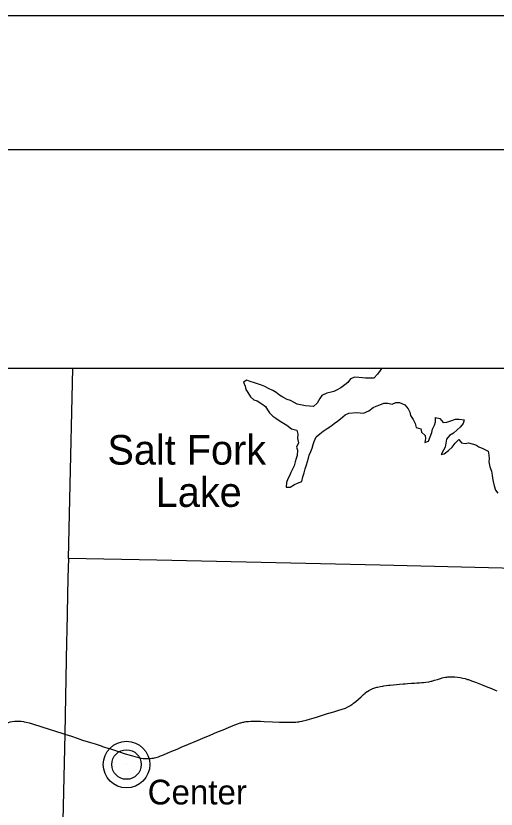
# Model space of a CAD drawing. Extents: x -29.6 to 34, y 0 to 22.
# Drawn here: x 7.023 to 8.82, y 19.03 to 22 of the extents above; entities that cross this region are included whole.
import ezdxf

# ---------------------------------------------------------------- set-up
doc = ezdxf.new("R2010")
doc.units = 0
for name, color, linetype in [('GM_X_Major_Lake', 7, 'Continuous'), ('GM_X_Major_Lake_Text', 7, 'Continuous'), ('GM_X_Township', 7, 'Continuous'), ('GM_X_Unincorporated', 7, 'Continuous'), ('GM_X_Unincorporated_Location', 7, 'Continuous'), ('GM_X_Unincorporated_Text', 7, 'Continuous'), ('GM_X_US_Route', 7, 'Continuous'), ('SH_Border', 7, 'Continuous'), ('SH_Cut_Line', 7, 'Continuous'), ('SH_Text', 7, 'Continuous')]:
    doc.layers.add(name, color=color, linetype=linetype)

msp = doc.modelspace()

# ---------------------------------------------------------------- linework, layer by layer
at = {"layer": 'GM_X_Major_Lake'}
for points in [[(8.3904, 20.6798), (8.3859, 20.672), (8.3754, 20.6581), (8.3617, 20.6442), (8.3493, 20.6437), (8.3312, 20.6436), (8.3196, 20.6448), (8.3064, 20.6461), (8.2917, 20.6477), (8.2749, 20.6414), (8.2653, 20.6271), (8.2534, 20.619), (8.2389, 20.6074), (8.2252, 20.5993), (8.2128, 20.5939), (8.1982, 20.5902), (8.1858, 20.587), (8.1682, 20.5789), (8.1603, 20.5669), (8.1507, 20.5499)], [(8.1507, 20.5499), (8.137, 20.5378), (8.1211, 20.5386), (8.106, 20.5394), (8.0758, 20.5467), (8.0647, 20.552), (8.0505, 20.5594), (8.0376, 20.5642), (8.0221, 20.5725), (8.0096, 20.5795), (7.9967, 20.5901), (7.9847, 20.5976), (7.9683, 20.6046), (7.954, 20.6129), (7.9421, 20.6177), (7.931, 20.6216), (7.9159, 20.626), (7.8994, 20.6316), (7.8875, 20.6355), (7.8742, 20.6283), (7.881, 20.6133), (7.8828, 20.6017), (7.8904, 20.5902), (7.9012, 20.5734), (7.9128, 20.5624), (7.9256, 20.5585), (7.943, 20.548), (7.9563, 20.5374), (7.9648, 20.5255), (7.9715, 20.514), (7.984, 20.5007), (7.9952, 20.4937), (8.0121, 20.4832), (8.0241, 20.4748), (8.037, 20.4674), (8.0543, 20.4533), (8.0747, 20.4494), (8.0779, 20.4343), (8.0767, 20.4183), (8.0799, 20.4019), (8.0734, 20.3854), (8.077, 20.3739), (8.0754, 20.3544), (8.0719, 20.3432), (8.068, 20.3303), (8.0637, 20.3152), (8.0585, 20.3027), (8.0519, 20.2902), (8.0463, 20.2782), (8.041, 20.2666), (8.0349, 20.2532), (8.0337, 20.2359), (8.0497, 20.2356), (8.0655, 20.2455), (8.077, 20.25), (8.0925, 20.2568), (8.0963, 20.2737), (8.1015, 20.2888), (8.1059, 20.3039), (8.1106, 20.3195), (8.1136, 20.3315), (8.1175, 20.344), (8.1206, 20.3551), (8.1267, 20.3689), (8.1319, 20.3819), (8.1354, 20.3948), (8.1393, 20.4068), (8.1462, 20.4237), (8.1599, 20.4349), (8.1727, 20.4448), (8.1881, 20.4551), (8.2013, 20.4637), (8.2141, 20.474), (8.2264, 20.4825), (8.2379, 20.4919), (8.2546, 20.5058), (8.2687, 20.5121), (8.298, 20.5145), (8.3117, 20.5142), (8.3232, 20.5121), (8.344, 20.5211), (8.3594, 20.5336), (8.3709, 20.5386), (8.3846, 20.544), (8.3991, 20.5495), (8.4146, 20.5496), (8.4306, 20.5461), (8.4443, 20.5529), (8.4585, 20.553), (8.478, 20.5438), (8.491, 20.5288), (8.4964, 20.516), (8.5, 20.5044), (8.5089, 20.4889), (8.517, 20.4739), (8.5211, 20.4593), (8.5384, 20.4541), (8.5412, 20.4412), (8.5541, 20.4289), (8.5551, 20.4173), (8.5529, 20.4031)], [(8.5529, 20.4031), (8.5662, 20.4081), (8.5727, 20.4237), (8.5793, 20.4401), (8.5823, 20.453), (8.5888, 20.4678), (8.5927, 20.4802), (8.5935, 20.4962), (8.6095, 20.4928), (8.6215, 20.4773), (8.6352, 20.4787), (8.6507, 20.4837), (8.6679, 20.4896), (8.6821, 20.4906), (8.7007, 20.4881), (8.6964, 20.4738), (8.6859, 20.4604), (8.6744, 20.4497), (8.6599, 20.4376), (8.6449, 20.4291), (8.6339, 20.4157), (8.6318, 20.4005), (8.6292, 20.385), (8.6231, 20.3734), (8.6144, 20.3578), (8.6259, 20.3601), (8.6422, 20.3731), (8.6549, 20.3852), (8.6668, 20.4003), (8.68, 20.4138), (8.6902, 20.4014), (8.7044, 20.3984), (8.7159, 20.4011), (8.7301, 20.3981), (8.7443, 20.3938), (8.7555, 20.3863), (8.7701, 20.3798), (8.7901, 20.3697), (8.792, 20.3555), (8.7938, 20.3431), (8.793, 20.3306), (8.7967, 20.312), (8.8021, 20.2951), (8.8045, 20.2809), (8.8059, 20.2694), (8.8082, 20.257), (8.8123, 20.2401), (8.8181, 20.2242), (8.8257, 20.2127)]]:
    msp.add_lwpolyline(points, dxfattribs=at)
at = {"layer": 'GM_X_Township'}
for points in [[(13.2018, 20.6798), (13.1972, 20.4897), (13.1757, 19.8128), (12.0094, 19.8432), (11.9667, 19.8448), (10.3631, 19.8945), (8.3857, 19.9434), (7.5502, 19.9616), (7.2204, 19.9686), (7.2242, 20.1907), (7.2354, 20.6798)], [(7.2204, 19.9686), (7.2172, 19.8963), (7.2135, 19.6982), (7.2126, 19.6576), (7.206, 19.3116), (7.1752, 17.958), (7.1502, 17.1493)]]:
    msp.add_lwpolyline(points, dxfattribs=at)
at = {"layer": 'GM_X_Unincorporated'}
for radius in [0.0872, 0.0553]:
    msp.add_circle((7.4369, 19.197), radius, dxfattribs=at)
at = {"layer": 'GM_X_Unincorporated_Location'}
msp.add_line((7.4369, 19.197), (7.4369, 19.197), dxfattribs=at)
at = {"layer": 'GM_X_US_Route'}
for points in [[(7.564, 19.2293), (7.5685, 19.231), (7.6063, 19.2466), (7.6258, 19.2548), (7.6419, 19.2616), (7.6694, 19.2732), (7.7055, 19.2887), (7.731, 19.2994), (7.7478, 19.3063), (7.7666, 19.3142), (7.7814, 19.3204), (7.7981, 19.3276), (7.8189, 19.3363), (7.8356, 19.3432), (7.8463, 19.3474), (7.8563, 19.3508), (7.8621, 19.3528), (7.8645, 19.3536), (7.872, 19.3554), (7.8755, 19.3562), (7.8778, 19.3566), (7.8838, 19.3576), (7.8934, 19.3585), (7.902, 19.3589), (7.9056, 19.359), (7.9102, 19.3591), (7.925, 19.3591), (7.9388, 19.3588), (7.9523, 19.3583), (7.9834, 19.357), (8.0088, 19.356), (8.0319, 19.3553), (8.0459, 19.3553), (8.0501, 19.3553), (8.0534, 19.3554), (8.0563, 19.3554), (8.0599, 19.3556), (8.0642, 19.3558), (8.0679, 19.3561), (8.071, 19.3563), (8.0768, 19.3569), (8.0812, 19.3574), (8.086, 19.3584), (8.094, 19.3596), (8.0975, 19.3604), (8.1095, 19.3635), (8.1219, 19.3672), (8.139, 19.3724), (8.1509, 19.3761), (8.1664, 19.3809), (8.1887, 19.3876), (8.2126, 19.3944), (8.2316, 19.4), (8.2439, 19.404), (8.2562, 19.4086), (8.2652, 19.4125), (8.2729, 19.4167), (8.2803, 19.4214), (8.2825, 19.423), (8.2868, 19.4262), (8.2947, 19.4327), (8.305, 19.442), (8.3145, 19.451), (8.3236, 19.4594), (8.3294, 19.4643), (8.3316, 19.4662), (8.3367, 19.4699), (8.3385, 19.4711), (8.3433, 19.4741), (8.3458, 19.4755), (8.3508, 19.478), (8.3586, 19.4813), (8.3662, 19.484), (8.3731, 19.4861), (8.3761, 19.4869), (8.387, 19.4893), (8.3957, 19.4906), (8.3996, 19.4913), (8.4168, 19.4937), (8.4233, 19.4945), (8.4363, 19.496), (8.4589, 19.4982), (8.4715, 19.4993), (8.4789, 19.4997), (8.4882, 19.5004), (8.5032, 19.5015), (8.5147, 19.5021), (8.5237, 19.5025), (8.5331, 19.5033), (8.5414, 19.5039), (8.5485, 19.5043), (8.5571, 19.5053), (8.5676, 19.5068), (8.5769, 19.5088), (8.579, 19.5094), (8.5897, 19.5126), (8.6005, 19.5159), (8.6081, 19.5184), (8.6157, 19.5205), (8.6184, 19.5212), (8.6229, 19.5223), (8.6301, 19.5237), (8.6359, 19.5245), (8.6395, 19.525), (8.6435, 19.5253), (8.6487, 19.5256), (8.6541, 19.5258), (8.6652, 19.5254), (8.6754, 19.5246), (8.6857, 19.523), (8.6953, 19.521), (8.7041, 19.5188), (8.7131, 19.516), (8.716, 19.5151), (8.7276, 19.511), (8.7421, 19.5053), (8.755, 19.5002), (8.7679, 19.4951), (8.7822, 19.4895), (8.7929, 19.4853), (8.8028, 19.4813), (8.816, 19.4758), (8.8231, 19.4731)], [(6.8768, 19.3094), (6.8937, 19.3157), (6.9242, 19.3277), (6.9486, 19.3371), (6.9764, 19.3479), (6.9957, 19.3546), (7.002, 19.3564), (7.0092, 19.3578), (7.018, 19.359), (7.0275, 19.3597), (7.0314, 19.3599), (7.0337, 19.3598), (7.0348, 19.3598), (7.0383, 19.3596), (7.0422, 19.3593), (7.0509, 19.3581), (7.0542, 19.3574), (7.061, 19.3561), (7.073, 19.3531), (7.0856, 19.3494), (7.1196, 19.3385), (7.1981, 19.3137), (7.2062, 19.311)], [(7.2062, 19.311), (7.2306, 19.3029), (7.2526, 19.2954), (7.2727, 19.2889), (7.3018, 19.2798), (7.3199, 19.2741), (7.342, 19.2668), (7.3475, 19.265), (7.3707, 19.2575), (7.3738, 19.2565), (7.3884, 19.2518), (7.4071, 19.246), (7.432, 19.2377), (7.4507, 19.2317), (7.4677, 19.2266)], [(7.4677, 19.2266), (7.4778, 19.2243), (7.4852, 19.2225), (7.4919, 19.2212), (7.4993, 19.2201), (7.5069, 19.2194), (7.5149, 19.2192), (7.5222, 19.2196), (7.5253, 19.2198), (7.5313, 19.2203), (7.5381, 19.2214), (7.5414, 19.222), (7.5479, 19.2237), (7.5565, 19.2265), (7.564, 19.2293)]]:
    msp.add_lwpolyline(points, dxfattribs=at)
at = {"layer": 'SH_Border'}
msp.add_lwpolyline([(1.5, 21.5), (33.5, 21.5), (33.5, 0.5), (1.5, 0.5)], close=True, dxfattribs=at)
at = {"layer": 'SH_Cut_Line'}
msp.add_lwpolyline([(0, 0), (34, 0), (34, 22), (0, 22)], close=True, dxfattribs=at)
at = {"layer": 'SH_Text'}
msp.add_line((20.8747, 20.6798), (2.5893, 20.6798), dxfattribs=at)

# ---------------------------------------------------------------- texts
at = {"layer": 'GM_X_Major_Lake_Text'}
for s, rotation, p in [('Salt Fork', 359.9926, (7.3654, 20.3199)), ('Lake', 359.9927, (7.5462, 20.1616))]:
    msp.add_text(s, height=0.11097, rotation=rotation, dxfattribs=at).set_placement(p)
at = {"layer": 'GM_X_Unincorporated_Text'}
msp.add_text('Center', height=0.09255, rotation=0, dxfattribs=at).set_placement((7.5159, 19.0476))

doc.saveas('drawing.dxf')
